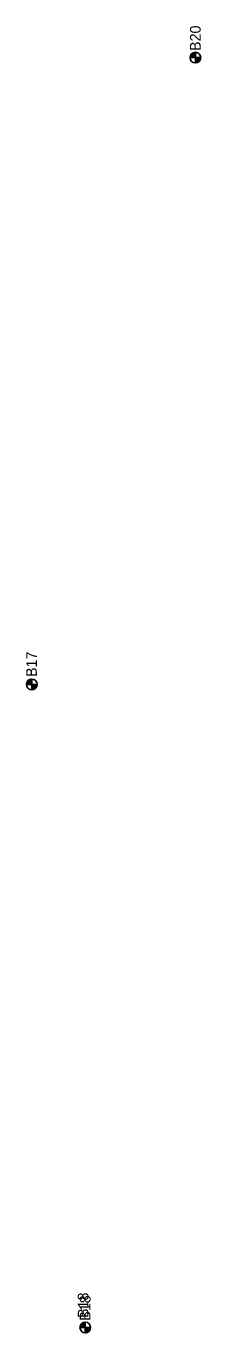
# Model space of a CAD drawing. Extents: x 311409 to 379449, y 121539 to 224848.
# Drawn here: x 361138 to 361301, y 137360 to 138586 of the extents above; entities that cross this region are included whole.
import ezdxf

# ---------------------------------------------------------------- set-up
doc = ezdxf.new("R2010")
doc.units = 0
for name, color, linetype in [('E_SOIL_BORE1 [KAPUR_CADDS_LEVELS]', 7, 'Continuous'), ('E_SOIL_BORE2 [KAPUR_CADDS_LEVELS]', 7, 'Continuous'), ('P_MARK', 7, 'Continuous')]:
    doc.layers.add(name, color=color, linetype=linetype)

msp = doc.modelspace()

# ---------------------------------------------------------------- linework, layer by layer
at = {"layer": 'P_MARK'}
for p, q in [((361296.3, 138561.1), (361296.3, 138551.1)), ((361291.3, 138556.1), (361301.3, 138556.1)), ((361143.1, 137973.3), (361143.1, 137963.3)), ((361138.1, 137968.3), (361148.1, 137968.3)), ((361188.2, 137365.2), (361198.2, 137365.2)), ((361193.2, 137370.2), (361193.2, 137360.2))]:
    msp.add_line(p, q, dxfattribs=at)
for centre in [(361296.3, 138556.1), (361143.1, 137968.3), (361193.2, 137365.2)]:
    msp.add_circle(centre, 5, dxfattribs=at)
for centre, radius, start, end in [((361296.3, 138556.1), 4.5, 89.9869, 179.9869), ((361296.3, 138556.1), 4, 89.9869, 179.9869), ((361296.3, 138556.1), 3.5, 89.9869, 179.9869), ((361296.3, 138556.1), 3, 89.9869, 179.9869), ((361296.3, 138556.1), 2.5, 89.9869, 179.9869), ((361296.3, 138556.1), 2, 89.9869, 179.9869), ((361296.3, 138556.1), 1.5, 89.9869, 179.9869), ((361296.3, 138556.1), 1, 89.9869, 179.9869), ((361296.3, 138556.1), 0.5, 89.9869, 179.9869), ((361296.3, 138556.1), 4.5, 269.9869, 359.9869), ((361296.3, 138556.1), 4, 269.9869, 359.9869), ((361296.3, 138556.1), 3.5, 269.9869, 359.9869), ((361296.3, 138556.1), 3, 269.9869, 359.9869), ((361296.3, 138556.1), 2.5, 269.9869, 359.9869), ((361296.3, 138556.1), 2, 269.9869, 359.9869), ((361296.3, 138556.1), 1.5, 269.9869, 359.9869), ((361296.3, 138556.1), 1, 269.9869, 359.9869), ((361296.3, 138556.1), 0.5, 269.9869, 359.9869), ((361143.1, 137968.3), 4.5, 89.9869, 179.9869), ((361143.1, 137968.3), 4, 89.9869, 179.9869), ((361143.1, 137968.3), 3.5, 89.9869, 179.9869), ((361143.1, 137968.3), 3, 89.9869, 179.9869), ((361143.1, 137968.3), 2.5, 89.9869, 179.9869), ((361143.1, 137968.3), 2, 89.9869, 179.9869), ((361143.1, 137968.3), 1.5, 89.9869, 179.9869), ((361143.1, 137968.3), 1, 89.9869, 179.9869), ((361143.1, 137968.3), 0.5, 89.9869, 179.9869), ((361143.1, 137968.3), 4.5, 269.9869, 359.9869), ((361143.1, 137968.3), 4, 269.9869, 359.9869), ((361143.1, 137968.3), 3.5, 269.9869, 359.9869), ((361143.1, 137968.3), 3, 269.9869, 359.9869), ((361143.1, 137968.3), 2.5, 269.9869, 359.9869), ((361143.1, 137968.3), 2, 269.9869, 359.9869), ((361143.1, 137968.3), 1.5, 269.9869, 359.9869), ((361143.1, 137968.3), 1, 269.9869, 359.9869), ((361143.1, 137968.3), 0.5, 269.9869, 359.9869), ((361193.2, 137365.2), 4.5, 89.9869, 179.9869), ((361193.2, 137365.2), 4, 89.9869, 179.9869), ((361193.2, 137365.2), 3.5, 89.9869, 179.9869), ((361193.2, 137365.2), 3, 89.9869, 179.9869), ((361193.2, 137365.2), 2.5, 89.9869, 179.9869), ((361193.2, 137365.2), 2, 89.9869, 179.9869), ((361193.2, 137365.2), 1.5, 89.9869, 179.9869), ((361193.2, 137365.2), 1, 89.9869, 179.9869), ((361193.2, 137365.2), 0.5, 89.9869, 179.9869), ((361193.2, 137365.2), 4.5, 269.9869, 359.9869), ((361193.2, 137365.2), 4, 269.9869, 359.9869), ((361193.2, 137365.2), 3.5, 269.9869, 359.9869), ((361193.2, 137365.2), 3, 269.9869, 359.9869), ((361193.2, 137365.2), 2.5, 269.9869, 359.9869), ((361193.2, 137365.2), 2, 269.9869, 359.9869), ((361193.2, 137365.2), 1.5, 269.9869, 359.9869), ((361193.2, 137365.2), 1, 269.9869, 359.9869), ((361193.2, 137365.2), 0.5, 269.9869, 359.9869)]:
    msp.add_arc(centre, radius, start, end, dxfattribs=at)

# ---------------------------------------------------------------- texts
at = {"layer": 'E_SOIL_BORE1 [KAPUR_CADDS_LEVELS]'}
for s, p in [('B20', (361301.3, 138562.4)), ('B17', (361147.9, 137975.3)), ('B18', (361196.2, 137374.2))]:
    msp.add_text(s, height=10, rotation=89.9869, dxfattribs=at).set_placement(p)
at = {"layer": 'E_SOIL_BORE2 [KAPUR_CADDS_LEVELS]'}
msp.add_text('B18', height=10, rotation=89.9869, dxfattribs=at).set_placement((361198.1, 137371.6))

doc.saveas('drawing.dxf')
